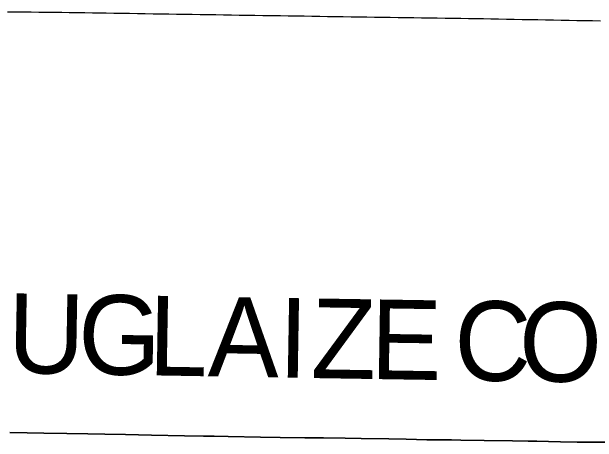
# Model space of a CAD drawing. Extents: x 0 to 34, y 0 to 22.
# Drawn here: x 5.2795 to 5.3978, y 19.4 to 19.4869 of the extents above; entities that cross this region are included whole.
import ezdxf

# ---------------------------------------------------------------- set-up
doc = ezdxf.new("R2010")
doc.units = 0
for name, color, linetype in [('GM_X_County', 7, 'Continuous'), ('GM_X_County_Text', 7, 'Continuous'), ('GM_X_State_Route', 7, 'Continuous')]:
    doc.layers.add(name, color=color, linetype=linetype)

msp = doc.modelspace()

# ---------------------------------------------------------------- linework, layer by layer
at = {"layer": 'GM_X_County'}
for points in [[(5.279146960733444, 19.401964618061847), (5.282680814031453, 19.401911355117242), (5.286055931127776, 19.401854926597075), (5.290643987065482, 19.401761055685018), (5.29491509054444, 19.401674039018), (5.298342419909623, 19.401616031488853), (5.302509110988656, 19.401547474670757), (5.307781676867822, 19.401458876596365), (5.314426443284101, 19.4013280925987), (5.318276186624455, 19.40125689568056), (5.32043732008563, 19.401214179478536), (5.323232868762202, 19.40117199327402), (5.329772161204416, 19.401057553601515), (5.33372632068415, 19.400996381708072), (5.338736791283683, 19.400930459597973), (5.342480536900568, 19.400867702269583), (5.346858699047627, 19.400821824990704), (5.350127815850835, 19.400752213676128), (5.355718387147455, 19.400669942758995), (5.359198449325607, 19.400617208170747), (5.363364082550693, 19.400526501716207), (5.368374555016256, 19.400464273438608), (5.3702197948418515, 19.40043263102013), (5.374913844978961, 19.400380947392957), (5.38066262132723, 19.400290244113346), (5.3838262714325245, 19.40023275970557), (5.385567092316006, 19.400196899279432), (5.387938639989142, 19.400135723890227), (5.390365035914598, 19.400109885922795), (5.3936853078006, 19.400052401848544), (5.396744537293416, 19.400048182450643), (5.401333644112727, 19.4000007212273)], [(5.401333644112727, 19.4000007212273), (5.396744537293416, 19.400048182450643), (5.3936853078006, 19.400052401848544), (5.390365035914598, 19.400109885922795), (5.387938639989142, 19.400135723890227), (5.385567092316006, 19.400196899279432), (5.3838262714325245, 19.40023275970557), (5.38066262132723, 19.400290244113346), (5.374913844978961, 19.400380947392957), (5.3702197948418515, 19.40043263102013), (5.368374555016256, 19.400464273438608), (5.363364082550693, 19.400526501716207), (5.359198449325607, 19.400617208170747), (5.355718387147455, 19.400669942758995), (5.350127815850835, 19.400752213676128), (5.346858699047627, 19.400821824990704), (5.342480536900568, 19.400867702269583), (5.338736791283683, 19.400930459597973), (5.33372632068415, 19.400996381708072), (5.329772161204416, 19.401057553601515), (5.323232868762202, 19.40117199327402), (5.32043732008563, 19.401214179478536), (5.318276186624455, 19.40125689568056), (5.314426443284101, 19.4013280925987), (5.307781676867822, 19.401458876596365), (5.302509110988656, 19.401547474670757), (5.298342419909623, 19.401616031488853), (5.29491509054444, 19.401674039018), (5.290643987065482, 19.401761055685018), (5.286055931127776, 19.401854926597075), (5.282680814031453, 19.401911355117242), (5.279146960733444, 19.401964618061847)]]:
    msp.add_lwpolyline(points, dxfattribs=at)
at = {"layer": 'GM_X_State_Route'}
msp.add_lwpolyline([(5.278710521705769, 19.48690518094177), (5.280292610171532, 19.486887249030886), (5.281874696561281, 19.486869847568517), (5.283456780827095, 19.48685191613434), (5.285038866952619, 19.486834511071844), (5.286620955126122, 19.486816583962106), (5.288203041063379, 19.48679917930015), (5.289664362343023, 19.486782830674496), (5.291126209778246, 19.486766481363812), (5.292708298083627, 19.48674222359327), (5.294290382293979, 19.486717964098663), (5.295872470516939, 19.48669370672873), (5.297234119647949, 19.48667261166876), (5.298595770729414, 19.4866520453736), (5.3001778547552, 19.486627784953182), (5.301759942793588, 19.486603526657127), (5.303342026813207, 19.486579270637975), (5.304924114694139, 19.48655500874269), (5.306506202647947, 19.486530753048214), (5.308088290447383, 19.48650649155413), (5.309670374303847, 19.486482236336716), (5.311252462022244, 19.486457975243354), (5.312834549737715, 19.48643371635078), (5.314416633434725, 19.486409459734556), (5.315998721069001, 19.486385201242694), (5.317580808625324, 19.486360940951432), (5.319162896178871, 19.486336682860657), (5.32074498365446, 19.48631242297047), (5.322327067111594, 19.48628816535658), (5.323909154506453, 19.486263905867), (5.3254912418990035, 19.486239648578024), (5.327073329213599, 19.486215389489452), (5.328655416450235, 19.48619112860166), (5.330237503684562, 19.486166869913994), (5.331819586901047, 19.486142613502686), (5.332817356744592, 19.48612732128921), (5.333815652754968, 19.486112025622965), (5.335397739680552, 19.48608882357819), (5.336979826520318, 19.486065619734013), (5.338561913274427, 19.486042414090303), (5.340144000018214, 19.486019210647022), (5.3417260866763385, 19.485996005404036), (5.343308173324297, 19.485972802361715), (5.344890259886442, 19.485949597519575), (5.346472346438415, 19.485926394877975), (5.348054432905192, 19.485903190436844), (5.3496365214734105, 19.48587945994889), (5.351218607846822, 19.485856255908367), (5.352800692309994, 19.485832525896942), (5.354382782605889, 19.485809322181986), (5.355964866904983, 19.485785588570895), (5.35754695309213, 19.485762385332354), (5.3591290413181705, 19.485738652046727), (5.360711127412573, 19.485715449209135), (5.362293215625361, 19.485691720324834), (5.36387530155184, 19.485668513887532), (5.365457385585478, 19.485644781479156), (5.367039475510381, 19.48562157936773), (5.368621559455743, 19.48559784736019), (5.3702036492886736, 19.485574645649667), (5.3717857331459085, 19.48555091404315), (5.373367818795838, 19.48552770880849), (5.374816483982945, 19.48550608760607), (5.376265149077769, 19.485484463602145), (5.377846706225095, 19.48545493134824), (5.379428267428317, 19.48542540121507), (5.381009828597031, 19.48539586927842), (5.3825913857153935, 19.4853663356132), (5.384172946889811, 19.485336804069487), (5.385754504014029, 19.485307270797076), (5.387336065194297, 19.485277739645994), (5.38891762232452, 19.48524820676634), (5.390499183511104, 19.48521867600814), (5.392080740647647, 19.48518914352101), (5.393662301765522, 19.485159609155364), (5.395243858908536, 19.48513007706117), (5.3968254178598, 19.485101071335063), (5.39840697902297, 19.485071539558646)], dxfattribs=at)

# ---------------------------------------------------------------- texts
at = {"layer": 'GM_X_County_Text'}
for s, height, rotation, p in [('U', 0.016074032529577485, 359.021566, (5.2786418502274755, 19.414011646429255)), ('G', 0.016074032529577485, 359.021566, (5.292855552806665, 19.413768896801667)), ('L', 0.016074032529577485, 359.022513, (5.307069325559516, 19.41352614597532)), ('A', 0.016074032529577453, 359.03162299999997, (5.319091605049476, 19.41332102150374)), ('I', 0.016074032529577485, 359.051073, (5.333306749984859, 19.413080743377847)), ('Z', 0.016074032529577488, 359.080703, (5.339885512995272, 19.412971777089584)), ('E', 0.016074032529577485, 359.104163, (5.351909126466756, 19.412778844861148)), ('C', 0.016074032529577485, 359.183308, (5.36881641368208, 19.41251624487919)), ('O', 0.016074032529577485, 359.243691, (5.3819038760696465, 19.41232968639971))]:
    msp.add_text(s, height=height, rotation=rotation, dxfattribs=at).set_placement(p)

doc.saveas('drawing.dxf')
